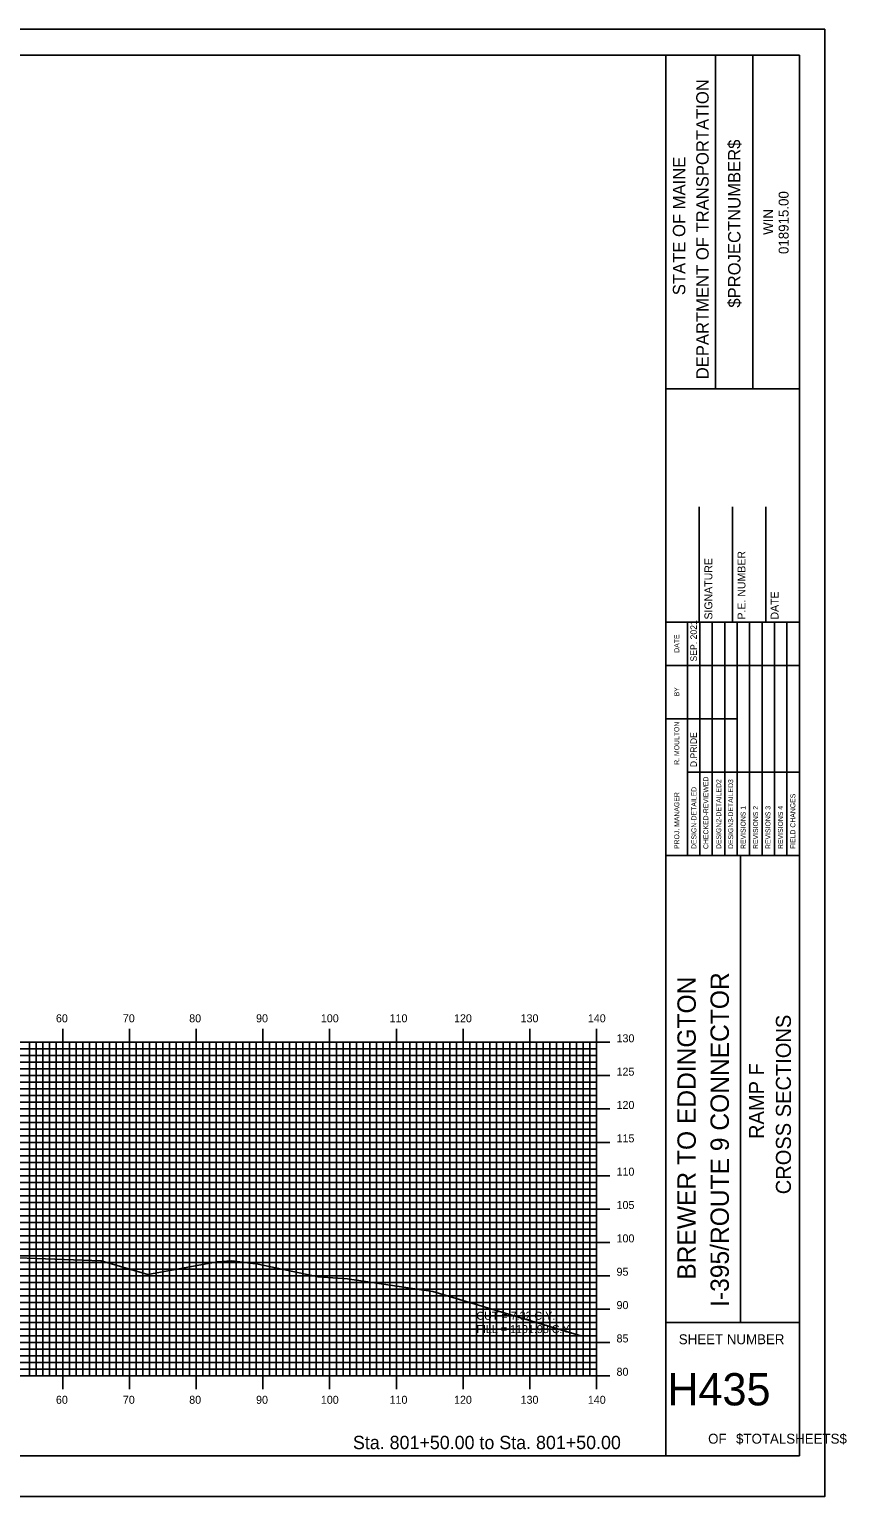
# Model space of a CAD drawing. Extents: x -695 to -352, y -1658 to -1438.
# Drawn here: x -474.4 to -351.9, y -1657.7 to -1437.7 of the extents above; entities that cross this region are included whole.
import ezdxf

# ---------------------------------------------------------------- set-up
doc = ezdxf.new("R2010")
doc.units = 0
for name, color, linetype in [('BORDER', 7, 'Continuous'), ('D_Text_Standard', 7, 'Continuous'), ('H_V ANNOTATION', 7, 'Continuous'), ('MAJOR', 7, 'Continuous'), ('MINOR', 7, 'Continuous'), ('PLOT BOUNDARY', 7, 'Continuous'), ('S_Roadway_Centerline', 7, 'Continuous')]:
    doc.layers.add(name, color=color, linetype=linetype)

msp = doc.modelspace()

# ---------------------------------------------------------------- linework, layer by layer
at = {"layer": 'BORDER'}
for p, q in [((-379, -1651.6), (-379, -1441.6)), ((-371.55, -1491.61), (-371.55, -1441.61)), ((-365.96, -1491.61), (-365.96, -1441.61)), ((-379, -1491.62), (-359, -1491.62)), ((-374, -1526.6), (-374, -1509.3)), ((-369, -1526.6), (-369, -1509.3)), ((-364, -1526.6), (-364, -1509.3)), ((-379, -1526.6), (-359, -1526.6)), ((-379, -1561.6), (-359, -1561.6)), ((-367.82, -1631.6), (-367.82, -1561.6)), ((-379, -1631.6), (-359, -1631.6))]:
    msp.add_line(p, q, dxfattribs=at)
msp.add_lwpolyline([(-679, -1651.6), (-359, -1651.6), (-359, -1441.6), (-679, -1441.6)], close=True, dxfattribs=at)
for points in [[(-375.78, -1533.1), (-375.78, -1526.6)], [(-373.91, -1561.59), (-373.91, -1526.6)], [(-372.05, -1526.6), (-372.05, -1561.59)], [(-370.18, -1561.59), (-370.18, -1526.6)], [(-368.32, -1561.59), (-368.32, -1526.6)], [(-366.46, -1561.59), (-366.46, -1526.6)], [(-364.59, -1561.59), (-364.59, -1526.6)], [(-362.73, -1561.59), (-362.73, -1526.6)], [(-360.87, -1561.59), (-360.87, -1526.6)], [(-375.77, -1561.59), (-375.77, -1528.01)], [(-379, -1533.1), (-359, -1533.1)], [(-379, -1541.1), (-375.77, -1541.1)], [(-375.78, -1541.1), (-368.32, -1541.1)], [(-375.78, -1549.1), (-359, -1549.1)]]:
    msp.add_lwpolyline(points, dxfattribs=at)
at = {"layer": 'MAJOR'}
for p, q in [((-469.4, -1587.6), (-469.4, -1589.6)), ((-459.4, -1587.6), (-459.4, -1589.6)), ((-449.4, -1587.6), (-449.4, -1589.6)), ((-439.4, -1587.6), (-439.4, -1589.6)), ((-429.4, -1587.6), (-429.4, -1589.6)), ((-419.4, -1587.6), (-419.4, -1589.6)), ((-409.4, -1587.6), (-409.4, -1589.6)), ((-399.4, -1587.6), (-399.4, -1589.6)), ((-389.4, -1587.6), (-389.4, -1589.6)), ((-669.4, -1589.6), (-389.4, -1589.6)), ((-669.4, -1589.6), (-389.4, -1589.6)), ((-469.4, -1639.6), (-469.4, -1589.6)), ((-459.4, -1639.6), (-459.4, -1589.6)), ((-449.4, -1639.6), (-449.4, -1589.6)), ((-439.4, -1639.6), (-439.4, -1589.6)), ((-429.4, -1639.6), (-429.4, -1589.6)), ((-419.4, -1639.6), (-419.4, -1589.6)), ((-409.4, -1639.6), (-409.4, -1589.6)), ((-399.4, -1639.6), (-399.4, -1589.6)), ((-387.4, -1589.6), (-391.41, -1589.6)), ((-389.4, -1639.6), (-389.4, -1589.6)), ((-389.4, -1639.6), (-389.4, -1589.6)), ((-669.4, -1594.6), (-389.4, -1594.6)), ((-387.4, -1594.6), (-391.41, -1594.6)), ((-669.4, -1599.6), (-389.4, -1599.6)), ((-387.4, -1599.6), (-391.41, -1599.6)), ((-669.4, -1604.6), (-389.4, -1604.6)), ((-387.4, -1604.6), (-391.41, -1604.6)), ((-669.4, -1609.6), (-389.4, -1609.6)), ((-387.4, -1609.6), (-391.41, -1609.6)), ((-669.4, -1614.6), (-389.4, -1614.6)), ((-387.4, -1614.6), (-391.41, -1614.6)), ((-669.4, -1619.6), (-389.4, -1619.6)), ((-387.4, -1619.6), (-391.41, -1619.6)), ((-669.4, -1624.6), (-389.4, -1624.6)), ((-387.4, -1624.6), (-391.41, -1624.6)), ((-669.4, -1629.6), (-389.4, -1629.6)), ((-387.4, -1629.6), (-391.41, -1629.6)), ((-669.4, -1634.6), (-389.4, -1634.6)), ((-387.4, -1634.6), (-391.41, -1634.6)), ((-669.4, -1639.6), (-389.4, -1639.6)), ((-669.4, -1639.6), (-389.4, -1639.6)), ((-469.4, -1641.61), (-469.4, -1639.6)), ((-459.4, -1641.61), (-459.4, -1639.6)), ((-449.4, -1641.61), (-449.4, -1639.6)), ((-439.4, -1641.61), (-439.4, -1639.6)), ((-429.4, -1641.61), (-429.4, -1639.6)), ((-419.4, -1641.61), (-419.4, -1639.6)), ((-409.4, -1641.61), (-409.4, -1639.6)), ((-399.4, -1641.61), (-399.4, -1639.6)), ((-387.4, -1639.6), (-391.41, -1639.6)), ((-389.4, -1641.61), (-389.4, -1639.6))]:
    msp.add_line(p, q, dxfattribs=at)
at = {"layer": 'MINOR'}
for p, q in [((-474.4, -1639.6), (-474.4, -1589.6)), ((-473.4, -1639.6), (-473.4, -1589.6)), ((-472.4, -1639.6), (-472.4, -1589.6)), ((-471.4, -1639.6), (-471.4, -1589.6)), ((-470.4, -1639.6), (-470.4, -1589.6)), ((-468.4, -1639.6), (-468.4, -1589.6)), ((-467.4, -1639.6), (-467.4, -1589.6)), ((-466.4, -1639.6), (-466.4, -1589.6)), ((-465.4, -1639.6), (-465.4, -1589.6)), ((-464.4, -1639.6), (-464.4, -1589.6)), ((-463.4, -1639.6), (-463.4, -1589.6)), ((-462.4, -1639.6), (-462.4, -1589.6)), ((-461.4, -1639.6), (-461.4, -1589.6)), ((-460.4, -1639.6), (-460.4, -1589.6)), ((-458.4, -1639.6), (-458.4, -1589.6)), ((-457.4, -1639.6), (-457.4, -1589.6)), ((-456.4, -1639.6), (-456.4, -1589.6)), ((-455.4, -1639.6), (-455.4, -1589.6)), ((-454.4, -1639.6), (-454.4, -1589.6)), ((-453.4, -1639.6), (-453.4, -1589.6)), ((-452.4, -1639.6), (-452.4, -1589.6)), ((-451.4, -1639.6), (-451.4, -1589.6)), ((-450.4, -1639.6), (-450.4, -1589.6)), ((-448.4, -1639.6), (-448.4, -1589.6)), ((-447.4, -1639.6), (-447.4, -1589.6)), ((-446.4, -1639.6), (-446.4, -1589.6)), ((-445.4, -1639.6), (-445.4, -1589.6)), ((-444.4, -1639.6), (-444.4, -1589.6)), ((-443.4, -1639.6), (-443.4, -1589.6)), ((-442.4, -1639.6), (-442.4, -1589.6)), ((-441.4, -1639.6), (-441.4, -1589.6)), ((-440.4, -1639.6), (-440.4, -1589.6)), ((-438.4, -1639.6), (-438.4, -1589.6)), ((-437.4, -1639.6), (-437.4, -1589.6)), ((-436.4, -1639.6), (-436.4, -1589.6)), ((-435.4, -1639.6), (-435.4, -1589.6)), ((-434.4, -1639.6), (-434.4, -1589.6)), ((-433.4, -1639.6), (-433.4, -1589.6)), ((-432.4, -1639.6), (-432.4, -1589.6)), ((-431.4, -1639.6), (-431.4, -1589.6)), ((-430.4, -1639.6), (-430.4, -1589.6)), ((-428.4, -1639.6), (-428.4, -1589.6)), ((-427.4, -1639.6), (-427.4, -1589.6)), ((-426.4, -1639.6), (-426.4, -1589.6)), ((-425.4, -1639.6), (-425.4, -1589.6)), ((-424.4, -1639.6), (-424.4, -1589.6)), ((-423.4, -1639.6), (-423.4, -1589.6)), ((-422.4, -1639.6), (-422.4, -1589.6)), ((-421.4, -1639.6), (-421.4, -1589.6)), ((-420.4, -1639.6), (-420.4, -1589.6)), ((-418.4, -1639.6), (-418.4, -1589.6)), ((-417.4, -1639.6), (-417.4, -1589.6)), ((-416.4, -1639.6), (-416.4, -1589.6)), ((-415.4, -1639.6), (-415.4, -1589.6)), ((-414.4, -1639.6), (-414.4, -1589.6)), ((-413.4, -1639.6), (-413.4, -1589.6)), ((-412.4, -1639.6), (-412.4, -1589.6)), ((-411.4, -1639.6), (-411.4, -1589.6)), ((-410.4, -1639.6), (-410.4, -1589.6)), ((-408.4, -1639.6), (-408.4, -1589.6)), ((-407.4, -1639.6), (-407.4, -1589.6)), ((-406.4, -1639.6), (-406.4, -1589.6)), ((-405.4, -1639.6), (-405.4, -1589.6)), ((-404.4, -1639.6), (-404.4, -1589.6)), ((-403.4, -1639.6), (-403.4, -1589.6)), ((-402.4, -1639.6), (-402.4, -1589.6)), ((-401.4, -1639.6), (-401.4, -1589.6)), ((-400.4, -1639.6), (-400.4, -1589.6)), ((-398.4, -1639.6), (-398.4, -1589.6)), ((-397.4, -1639.6), (-397.4, -1589.6)), ((-396.4, -1639.6), (-396.4, -1589.6)), ((-395.4, -1639.6), (-395.4, -1589.6)), ((-394.4, -1639.6), (-394.4, -1589.6)), ((-393.4, -1639.6), (-393.4, -1589.6)), ((-392.4, -1639.6), (-392.4, -1589.6)), ((-391.4, -1639.6), (-391.4, -1589.6)), ((-390.4, -1639.6), (-390.4, -1589.6)), ((-669.4, -1590.6), (-389.4, -1590.6)), ((-669.4, -1591.6), (-389.4, -1591.6)), ((-669.4, -1592.6), (-389.4, -1592.6)), ((-389.4, -1590.6), (-391.41, -1590.6)), ((-389.4, -1591.6), (-391.41, -1591.6)), ((-389.4, -1592.6), (-391.41, -1592.6)), ((-669.4, -1593.6), (-389.4, -1593.6)), ((-389.4, -1593.6), (-391.41, -1593.6)), ((-669.4, -1595.6), (-389.4, -1595.6)), ((-669.4, -1596.6), (-389.4, -1596.6)), ((-389.4, -1595.6), (-391.41, -1595.6)), ((-389.4, -1596.6), (-391.41, -1596.6)), ((-669.4, -1597.6), (-389.4, -1597.6)), ((-669.4, -1598.6), (-389.4, -1598.6)), ((-389.4, -1597.6), (-391.41, -1597.6)), ((-389.4, -1598.6), (-391.41, -1598.6)), ((-669.4, -1600.6), (-389.4, -1600.6)), ((-389.4, -1600.6), (-391.41, -1600.6)), ((-669.4, -1601.6), (-389.4, -1601.6)), ((-669.4, -1602.6), (-389.4, -1602.6)), ((-669.4, -1603.6), (-389.4, -1603.6)), ((-389.4, -1601.6), (-391.41, -1601.6)), ((-389.4, -1602.6), (-391.41, -1602.6)), ((-389.4, -1603.6), (-391.41, -1603.6)), ((-669.4, -1605.6), (-389.4, -1605.6)), ((-389.4, -1605.6), (-391.41, -1605.6)), ((-669.4, -1606.6), (-389.4, -1606.6)), ((-669.4, -1607.6), (-389.4, -1607.6)), ((-389.4, -1606.6), (-391.41, -1606.6)), ((-389.4, -1607.6), (-391.41, -1607.6)), ((-669.4, -1608.6), (-389.4, -1608.6)), ((-389.4, -1608.6), (-391.41, -1608.6)), ((-669.4, -1610.6), (-389.4, -1610.6)), ((-669.4, -1611.6), (-389.4, -1611.6)), ((-389.4, -1610.6), (-391.41, -1610.6)), ((-389.4, -1611.6), (-391.41, -1611.6)), ((-669.4, -1612.6), (-389.4, -1612.6)), ((-669.4, -1613.6), (-389.4, -1613.6)), ((-389.4, -1612.6), (-391.41, -1612.6)), ((-389.4, -1613.6), (-391.41, -1613.6)), ((-669.4, -1615.6), (-389.4, -1615.6)), ((-669.4, -1616.6), (-389.4, -1616.6)), ((-389.4, -1615.6), (-391.41, -1615.6)), ((-389.4, -1616.6), (-391.41, -1616.6)), ((-669.4, -1617.6), (-389.4, -1617.6)), ((-669.4, -1618.6), (-389.4, -1618.6)), ((-389.4, -1617.6), (-391.41, -1617.6)), ((-389.4, -1618.6), (-391.41, -1618.6)), ((-669.4, -1620.6), (-389.4, -1620.6)), ((-389.4, -1620.6), (-391.41, -1620.6)), ((-669.4, -1621.6), (-389.4, -1621.6)), ((-669.4, -1622.6), (-389.4, -1622.6)), ((-389.4, -1621.6), (-391.41, -1621.6)), ((-389.4, -1622.6), (-391.41, -1622.6)), ((-669.4, -1623.6), (-389.4, -1623.6)), ((-669.4, -1625.6), (-389.4, -1625.6)), ((-389.4, -1623.6), (-391.41, -1623.6)), ((-389.4, -1625.6), (-391.41, -1625.6)), ((-669.4, -1626.6), (-389.4, -1626.6)), ((-669.4, -1627.6), (-389.4, -1627.6)), ((-389.4, -1626.6), (-391.41, -1626.6)), ((-389.4, -1627.6), (-391.41, -1627.6)), ((-669.4, -1628.6), (-389.4, -1628.6)), ((-389.4, -1628.6), (-391.41, -1628.6)), ((-669.4, -1630.6), (-389.4, -1630.6)), ((-669.4, -1631.6), (-389.4, -1631.6)), ((-389.4, -1630.6), (-391.41, -1630.6)), ((-389.4, -1631.6), (-391.41, -1631.6)), ((-669.4, -1632.6), (-389.4, -1632.6)), ((-669.4, -1633.6), (-389.4, -1633.6)), ((-389.4, -1632.6), (-391.41, -1632.6)), ((-389.4, -1633.6), (-391.41, -1633.6)), ((-669.4, -1635.6), (-389.4, -1635.6)), ((-669.4, -1636.6), (-389.4, -1636.6)), ((-389.4, -1635.6), (-391.41, -1635.6)), ((-389.4, -1636.6), (-391.41, -1636.6)), ((-669.4, -1637.6), (-389.4, -1637.6)), ((-669.4, -1638.6), (-389.4, -1638.6)), ((-389.4, -1637.6), (-391.41, -1637.6)), ((-389.4, -1638.6), (-391.41, -1638.6))]:
    msp.add_line(p, q, dxfattribs=at)
at = {"layer": 'PLOT BOUNDARY'}
msp.add_lwpolyline([(-695.19, -1657.72), (-355.19, -1657.72), (-355.19, -1437.72), (-695.19, -1437.72)], close=True, dxfattribs=at)
at = {"layer": 'S_Roadway_Centerline'}
msp.add_lwpolyline([(-477.52, -1621.89), (-463.66, -1622.39), (-456.63, -1624.43), (-446.28, -1622.5), (-444.05, -1622.38), (-440.14, -1622.84), (-431.13, -1624.78), (-426.73, -1625.07), (-413.95, -1626.96), (-391.74, -1633.59), (-389.4, -1633.64)], dxfattribs=at)

# ---------------------------------------------------------------- texts
at = {"layer": 'BORDER'}
for s, height, p in [('DEPARTMENT OF TRANSPORTATION', 1.8635, (-372.59, -1490.19)), ('$PROJECTNUMBER$', 1.8635, (-367.82, -1479.45)), ('STATE OF MAINE', 1.8635, (-376.09, -1477.58)), ('018915.00', 1.491, (-360.61, -1471.41)), ('WIN', 1.491, (-362.93, -1468.54)), ('SIGNATURE', 1.181, (-372.04, -1526.21)), ('P.E. NUMBER', 1.1811, (-367.08, -1526.21)), ('DATE', 1.181, (-362.12, -1526.21)), ('SEP. 2021', 0.969, (-374.36, -1532.51)), ('DATE', 0.743, (-377, -1531.19)), ('BY', 0.743, (-377, -1537.73)), ('R. MOULTON', 0.745, (-377, -1547.99)), ('D.PRIDE', 0.969, (-374.36, -1548.35)), ('CHECKED-REVIEWED', 0.7455, (-372.64, -1560.62)), ('DESIGN2-DETAILED2', 0.7455, (-370.71, -1560.62)), ('DESIGN3-DETAILED3', 0.7455, (-368.92, -1560.62)), ('PROJ. MANAGER', 0.7455, (-377, -1560.62)), ('DESIGN-DETAILED', 0.7455, (-374.43, -1560.62)), ('FIELD CHANGES', 0.7455, (-359.6, -1560.62)), ('REVISIONS 1', 0.7455, (-367.05, -1560.62)), ('REVISIONS 2', 0.7455, (-365.19, -1560.62)), ('REVISIONS 3', 0.7455, (-363.33, -1560.62)), ('REVISIONS 4', 0.7455, (-361.46, -1560.62)), ('I-395/ROUTE 9 CONNECTOR', 2.7557, (-369.56, -1629.27)), ('BREWER TO EDDINGTON', 2.7557, (-374.52, -1625.2)), ('CROSS SECTIONS', 2.25, (-360.26, -1612.38)), ('RAMP F', 2.25, (-364.31, -1604.1))]:
    msp.add_text(s, height=height, rotation=90, dxfattribs=at).set_placement(p)
for s, height, p in [('SHEET NUMBER', 1.4905, (-377.07, -1634.87)), ('H435', 4.839, (-378.79, -1644.04)), ('OF', 1.491, (-372.67, -1649.78)), ('$TOTALSHEETS$', 1.4905, (-368.49, -1649.78))]:
    msp.add_text(s, height=height, dxfattribs=at).set_placement(p)
at = {"layer": 'D_Text_Standard'}
for s, p in [('CUT = 7.32 C.Y.', (-407.4, -1631.2)), ('FILL = 1101.98 C.Y.', (-407.4, -1633.2))]:
    msp.add_text(s, height=1.2, dxfattribs=at).set_placement(p)
at = {"layer": 'H_V ANNOTATION'}
for s, height, p in [('60', 1.2, (-470.43, -1586.6)), ('70', 1.2, (-460.4, -1586.6)), ('80', 1.2, (-450.45, -1586.6)), ('90', 1.2, (-440.43, -1586.6)), ('100', 1.2, (-430.72, -1586.6)), ('110', 1.2, (-420.42, -1586.6)), ('120', 1.2, (-410.76, -1586.6)), ('130', 1.2, (-400.78, -1586.6)), ('140', 1.2, (-390.7, -1586.6)), ('130', 1.2, (-386.4, -1589.6)), ('125', 1.2, (-386.4, -1594.6)), ('120', 1.2, (-386.4, -1599.6)), ('115', 1.2, (-386.4, -1604.6)), ('110', 1.2, (-386.4, -1609.6)), ('105', 1.2, (-386.4, -1614.6)), ('100', 1.2, (-386.4, -1619.6)), ('95', 1.2, (-386.4, -1624.6)), ('90', 1.2, (-386.4, -1629.6)), ('85', 1.2, (-386.4, -1634.6)), ('80', 1.2, (-386.4, -1639.6)), ('60', 1.2, (-470.43, -1643.8)), ('70', 1.2, (-460.4, -1643.8)), ('80', 1.2, (-450.45, -1643.8)), ('90', 1.2, (-440.43, -1643.8)), ('100', 1.2, (-430.72, -1643.8)), ('110', 1.2, (-420.42, -1643.8)), ('120', 1.2, (-410.76, -1643.8)), ('130', 1.2, (-400.78, -1643.8)), ('140', 1.2, (-390.7, -1643.8)), ('Sta. 801+50.00 to Sta. 801+50.00', 2.0004, (-425.91, -1650.6))]:
    msp.add_text(s, height=height, dxfattribs=at).set_placement(p)

doc.saveas('drawing.dxf')
